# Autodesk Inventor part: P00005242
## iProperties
Shininess: 64.0
Length Units: 11269
Angle Units: 11279
Time Units: 11290
Mass Units: 11283
Length Display Precision: 3
Angle Display Precision: 2
Compacted: True
Part Number: P00005242
Document SubType Name: Modeling
Created: 2004-01
Material: Stahl (schweißbar)
Designer: Mittelmeyer
Manufacturer: Standard
Standards Organization: Custom
Density: 0.0
Volumn: 0.0
Area: 0.0
PropertySet Name: Model Information
Control State: 0
Master: False
Checked Out: False
Author: Mittelmeyer
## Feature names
1. Basis1
